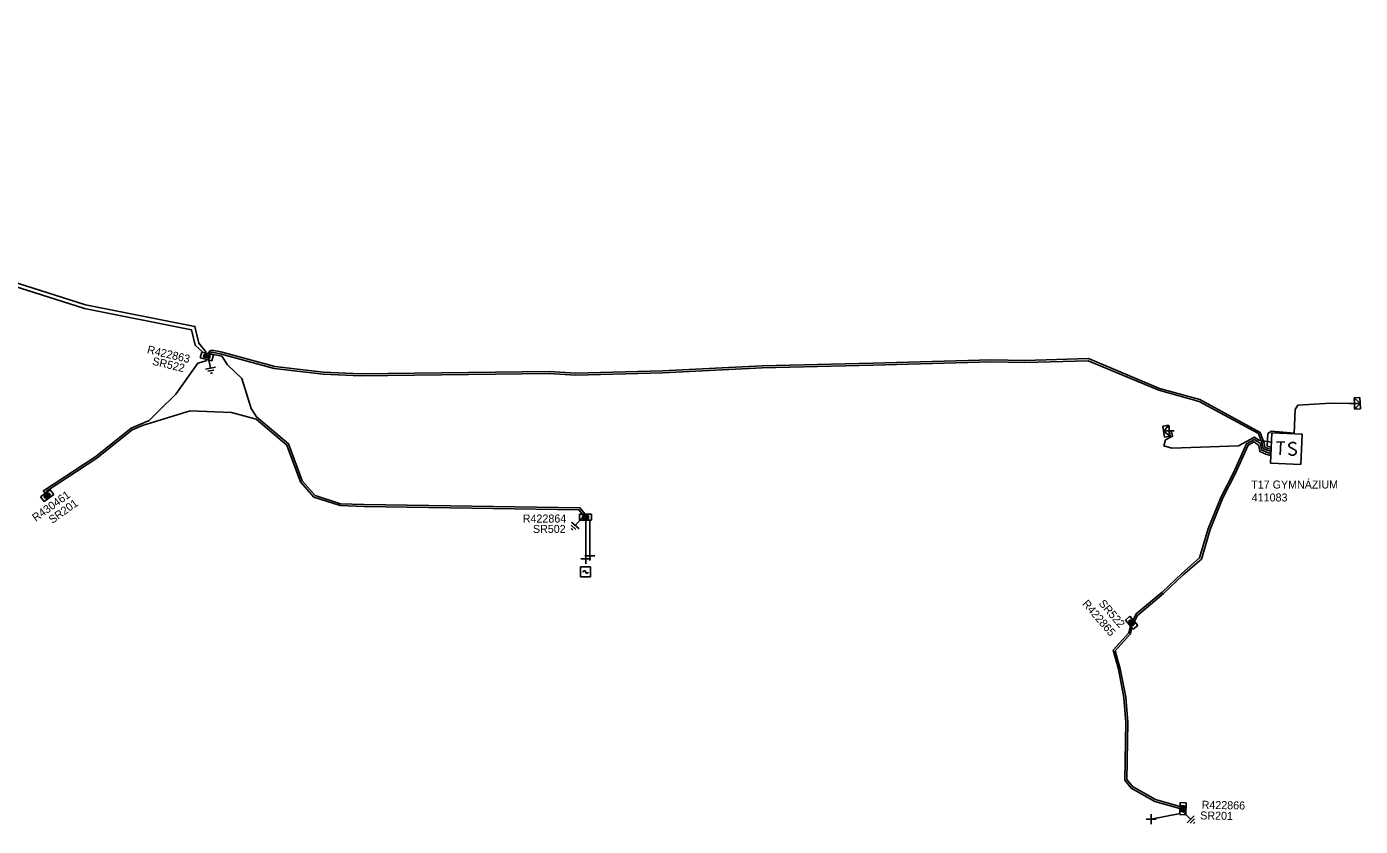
# Model space of a CAD drawing. Extents: x -540466 to -537383, y -1184038 to -1179972.
# Drawn here: x -537561.4 to -537394.7, y -1180860.1 to -1180760.2 of the extents above; entities that cross this region are included whole.
import ezdxf

# ---------------------------------------------------------------- set-up
doc = ezdxf.new("R2010")
doc.units = 0
for name, color, linetype in [('Vrstva 1', 7, 'Continuous'), ('Vrstva 14', 7, 'Continuous'), ('Vrstva 15', 7, 'Continuous'), ('Vrstva 25', 7, 'Continuous'), ('Vrstva 26', 7, 'Continuous'), ('Vrstva 27', 7, 'Continuous'), ('Vrstva 28', 7, 'Continuous'), ('Vrstva 29', 7, 'Continuous'), ('Vrstva 30', 7, 'Continuous'), ('Vrstva 31', 7, 'Continuous'), ('Vrstva 34', 7, 'Continuous'), ('Vrstva 5', 7, 'Continuous'), ('Vrstva 52', 7, 'Continuous'), ('Vrstva 59', 7, 'Continuous'), ('Vrstva 6', 7, 'Continuous'), ('Vrstva 8', 7, 'Continuous'), ('Vrstva 9', 7, 'Continuous')]:
    doc.layers.add(name, color=color, linetype=linetype)

# ---------------------------------------------------------------- blocks, each defined once
blk = doc.blocks.new('NN800')
at = {"layer": 'Vrstva 1'}
for points in [[(-0.44, 0.44), (0.44, -0.44)], [(-0.44, -0.44), (0.44, 0.44)]]:
    blk.add_lwpolyline(points, dxfattribs=at)
blk = doc.blocks.new('NN620')
at = {"layer": 'Vrstva 8'}
for points in [[(0.75, 0), (-0.75, 0)], [(-0.75, 0), (-0.75, -0.75)], [(0.75, -0.75), (0.75, 0)], [(-0.75, -0.75), (0.75, -0.75)], [(0.37, -0.18), (-0.38, -0.18)], [(-0.38, -0.18), (-0.38, -0.56)], [(-0.38, -0.56), (0.37, -0.56)], [(0.32, -0.23), (-0.33, -0.23)], [(-0.33, -0.23), (-0.33, -0.51)], [(-0.33, -0.51), (0.32, -0.51)], [(0.27, -0.27), (-0.28, -0.27)], [(-0.28, -0.27), (-0.28, -0.46)], [(-0.28, -0.46), (0.27, -0.46)], [(0.23, -0.32), (-0.23, -0.32)], [(-0.23, -0.32), (-0.23, -0.42)], [(-0.23, -0.42), (0.23, -0.42)], [(-0.19, -0.37), (0.19, -0.37)], [(0.23, -0.42), (0.23, -0.32)], [(0.27, -0.46), (0.27, -0.27)], [(0.32, -0.51), (0.32, -0.23)], [(0.37, -0.56), (0.37, -0.18)]]:
    blk.add_lwpolyline(points, dxfattribs=at)
blk = doc.blocks.new('NN630')
at = {"layer": 'Vrstva 9'}
for points in [[(0, -0.7), (-0.7, 0)], [(-0.7, -0.7), (-0.7, 0), (0.7, 0), (0.7, -0.7)], [(-0.7, -0.7), (0.7, -0.7)], [(0, -0.7), (0.7, 0)]]:
    blk.add_lwpolyline(points, dxfattribs=at)
blk = doc.blocks.new('NN810')
at = {"layer": 'Vrstva 14'}
for points in [[(0, -0.64), (0, -1.89)], [(0.63, -1.89), (-0.62, -1.89)], [(0.39, -2.2), (-0.4, -2.2)], [(0, -2.52), (-0.12, -2.52)], [(0.14, -2.52), (0, -2.52)]]:
    blk.add_lwpolyline(points, dxfattribs=at)
blk = doc.blocks.new('NN740')
at = {"layer": 'Vrstva 1'}
for points in [[(0.62, 0.62), (-0.63, 0.62)], [(-0.63, 0.62), (-0.63, -0.63)], [(0, 0), (0, 0.01), (0, 0.03), (-0.01, 0.05), (-0.01, 0.06), (-0.02, 0.08), (-0.03, 0.09), (-0.04, 0.1), (-0.05, 0.11), (-0.06, 0.12), (-0.08, 0.13), (-0.09, 0.14), (-0.11, 0.14), (-0.12, 0.15), (-0.14, 0.15), (-0.15, 0.15), (-0.17, 0.15), (-0.18, 0.15), (-0.2, 0.15), (-0.21, 0.14), (-0.23, 0.13), (-0.24, 0.12), (-0.26, 0.11), (-0.27, 0.1), (-0.28, 0.09), (-0.29, 0.08), (-0.29, 0.06), (-0.3, 0.05), (-0.3, 0.03), (-0.31, 0.02), (-0.31, 0), (-0.31, 0)], [(0.62, -0.63), (0.62, 0.62)], [(-0.63, -0.63), (0.62, -0.63)], [(0, 0), (0, -0.02), (0, -0.03), (0.01, -0.05), (0.01, -0.06), (0.02, -0.08), (0.03, -0.09), (0.04, -0.1), (0.05, -0.11), (0.06, -0.12), (0.07, -0.13), (0.09, -0.14), (0.1, -0.15), (0.12, -0.15), (0.13, -0.15), (0.15, -0.15), (0.16, -0.15), (0.18, -0.15), (0.19, -0.15), (0.21, -0.14), (0.22, -0.14), (0.24, -0.13), (0.25, -0.12), (0.26, -0.11), (0.27, -0.09), (0.28, -0.08), (0.29, -0.07), (0.29, -0.05), (0.3, -0.04), (0.3, -0.02), (0.3, -0.01), (0.3, -0.01)]]:
    blk.add_lwpolyline(points, dxfattribs=at)
blk = doc.blocks.new('NN640')
at = {"layer": 'Vrstva 6'}
for points in [[(-1.89, 1.89), (1.89, 1.89)], [(-1.89, -1.89), (-1.89, 1.89)], [(1.89, 1.89), (1.89, -1.89)], [(-1.26, 0.79), (-0.22, 0.79)], [(-0.73, 0.79), (-0.73, -0.79)], [(1.2, 0.66), (0.94, 0.79), (0.66, 0.79), (0.41, 0.66), (0.28, 0.47), (0.28, 0.41), (0.41, 0.22), (1.13, -0.16), (1.26, -0.32), (1.26, -0.47), (1.13, -0.66), (0.91, -0.79), (0.63, -0.79), (0.5, -0.73), (0.28, -0.6)], [(1.89, -1.89), (-1.89, -1.89)]]:
    blk.add_lwpolyline(points, dxfattribs=at)

msp = doc.modelspace()

# ---------------------------------------------------------------- linework, layer by layer
at = {"layer": 'Vrstva 5'}
for points in [[(-537539.27, -1180800.97), (-537540.33, -1180800.01), (-537540.77, -1180798.09), (-537554.14, -1180795.43), (-537572.94, -1180789.46), (-537579.99, -1180786.34), (-537583.4, -1180794.6), (-537583.56, -1180794.69), (-537583.6, -1180794.52), (-537580.17, -1180786.23), (-537584.61, -1180784.3), (-537592.51, -1180779.99), (-537605.42, -1180772.39), (-537614.61, -1180766.01), (-537620.35, -1180761.52), (-537621.15, -1180761.13), (-537621.78, -1180760.86), (-537622.41, -1180760.33)], [(-537539, -1180801.01), (-537538.98, -1180800.82), (-537539.87, -1180799.75), (-537540.35, -1180797.67), (-537554.02, -1180794.95), (-537572.76, -1180789), (-537584.39, -1180783.86), (-537592.27, -1180779.55), (-537605.16, -1180771.97), (-537614.31, -1180765.61), (-537620.03, -1180761.14), (-537621, -1180760.93), (-537621.67, -1180760.69), (-537622.25, -1180760.23)], [(-537538.74, -1180801.06), (-537538.46, -1180800.72), (-537538.21, -1180800.61), (-537537.13, -1180800.82), (-537530.39, -1180802.67), (-537524.33, -1180803.38), (-537519.64, -1180803.57), (-537496.09, -1180803.31), (-537492.78, -1180803.49), (-537481.94, -1180803.2), (-537469.47, -1180802.6), (-537455.67, -1180802.25), (-537440.83, -1180801.84), (-537436.67, -1180801.93), (-537428.72, -1180801.69), (-537419.84, -1180805.4), (-537414.79, -1180806.81), (-537407.24, -1180810.9), (-537406.74, -1180812.23), (-537406.65, -1180812.75), (-537406.29, -1180812.9), (-537405.94, -1180812.99)], [(-537538.48, -1180801.12), (-537538.32, -1180800.94), (-537538.18, -1180800.88), (-537537.19, -1180801.07), (-537530.44, -1180802.91), (-537524.35, -1180803.62), (-537519.64, -1180803.82), (-537496.09, -1180803.56), (-537492.78, -1180803.74), (-537481.93, -1180803.45), (-537469.47, -1180802.85), (-537455.67, -1180802.5), (-537440.83, -1180802.09), (-537436.67, -1180802.18), (-537428.76, -1180801.95), (-537419.92, -1180805.64), (-537414.89, -1180807.05), (-537407.46, -1180811.06), (-537406.99, -1180812.28), (-537406.87, -1180812.92), (-537406.37, -1180813.14), (-537405.95, -1180813.25)], [(-537491.58, -1180821.1), (-537492.25, -1180820.32), (-537519.19, -1180819.92), (-537522.15, -1180819.81), (-537525.35, -1180818.77), (-537526.94, -1180816.95), (-537528.66, -1180812.33), (-537532.65, -1180808.97), (-537533.31, -1180807.91), (-537534.5, -1180804.16), (-537536.29, -1180802.47), (-537537, -1180801.36), (-537538.23, -1180801.12), (-537538.29, -1180801.16)], [(-537538.91, -1180801.8), (-537538.94, -1180801.96), (-537540, -1180802.24), (-537542.72, -1180806.12), (-537544.8, -1180808.13), (-537546.07, -1180809.4), (-537548.33, -1180810.36), (-537552.75, -1180813.91), (-537559.28, -1180818.2), (-537559.06, -1180818.48)], [(-537558.86, -1180818.34), (-537558.92, -1180818.26), (-537552.61, -1180814.11), (-537548.19, -1180810.58), (-537546.91, -1180810.05), (-537540.94, -1180808.21), (-537535.77, -1180808.4), (-537532.72, -1180809.25), (-537528.88, -1180812.49), (-537527.16, -1180817.07), (-537525.49, -1180818.99), (-537522.19, -1180820.05), (-537519.19, -1180820.17), (-537492.37, -1180820.56), (-537491.91, -1180821.1)], [(-537423.1, -1180834.34), (-537422.74, -1180833.56), (-537419.49, -1180830.86), (-537417.03, -1180828.53), (-537414.82, -1180826.59), (-537413.73, -1180822.93), (-537412.14, -1180818.96), (-537410.59, -1180815.97), (-537408.96, -1180812.31), (-537407.98, -1180811.79), (-537407.23, -1180812.3), (-537407.09, -1180813.1), (-537406.45, -1180813.38), (-537406.04, -1180813.49), (-537405.96, -1180813.49)], [(-537422.95, -1180834.52), (-537422.58, -1180833.76), (-537419.33, -1180831.04), (-537416.87, -1180828.71), (-537414.6, -1180826.73), (-537413.49, -1180823.01), (-537411.92, -1180819.06), (-537410.37, -1180816.07), (-537408.76, -1180812.49), (-537408.02, -1180812.1), (-537407.43, -1180812.52), (-537407.31, -1180813.27), (-537406.53, -1180813.62), (-537406.07, -1180813.73), (-537405.96, -1180813.74)], [(-537417.3, -1180857.88), (-537420.41, -1180856.99), (-537423.37, -1180855.35), (-537424.18, -1180854.33), (-537424.05, -1180847.15), (-537424.28, -1180844), (-537424.97, -1180840.48), (-537425.64, -1180838.12), (-537423.66, -1180835.95), (-537423.45, -1180835.16)], [(-537417.3, -1180857.62), (-537420.31, -1180856.75), (-537423.21, -1180855.15), (-537423.92, -1180854.25), (-537423.8, -1180847.15), (-537424.04, -1180843.96), (-537424.73, -1180840.42), (-537425.36, -1180838.18), (-537423.48, -1180836.11), (-537423.27, -1180835.37)]]:
    msp.add_lwpolyline(points, dxfattribs=at)
at = {"layer": 'Vrstva 52'}
for points in [[(-537405.94, -1180812.74), (-537406.37, -1180812.62), (-537406.28, -1180811.04), (-537405.82, -1180810.75), (-537403, -1180810.99), (-537402.87, -1180808.04), (-537402.53, -1180807.48), (-537398.45, -1180807.23), (-537395.46, -1180807.29)], [(-537405.87, -1180812.11), (-537407.42, -1180811.87), (-537407.97, -1180811.49), (-537409.95, -1180812.57), (-537418.31, -1180812.86), (-537419.28, -1180812.59), (-537419.07, -1180811.84), (-537418.19, -1180811.39), (-537418.39, -1180810.67), (-537418.61, -1180810.69)]]:
    msp.add_lwpolyline(points, dxfattribs=at)
at = {"layer": 'Vrstva 59'}
for points in [[(-537491.49, -1180821.85), (-537491.51, -1180826.7)], [(-537491.02, -1180821.86), (-537491.02, -1180826.3)], [(-537417.25, -1180858.51), (-537420.86, -1180859.23)]]:
    msp.add_lwpolyline(points, dxfattribs=at)

# ---------------------------------------------------------------- block references
at = {"layer": 'Vrstva 15'}
for p, rotation in [((-537538.78, -1180801.03), 11.175980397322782), ((-537491.56, -1180821.13), -42.231711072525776), ((-537417.28, -1180857.89), 44.99999995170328)]:
    msp.add_blockref('NN810', p, dxfattribs=dict(at, rotation=rotation))
at = {"layer": 'Vrstva 25', "rotation": -2.259422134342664}
msp.add_blockref('NN640', (-537403.98, -1180812.93), dxfattribs=at)
at = {"layer": 'Vrstva 28'}
for p, rotation in [((-537538.78, -1180801.04), -13.436633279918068), ((-537559.04, -1180818.5), 35.721227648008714), ((-537423.04, -1180834.44), -49.09191936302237), ((-537417.28, -1180857.89), 88.96100838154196)]:
    msp.add_blockref('NN620', p, dxfattribs=dict(at, rotation=rotation))
msp.add_blockref('NN620', (-537491.56, -1180821.13), dxfattribs=at)
at = {"layer": 'Vrstva 31'}
for p, rotation in [((-537395.46, -1180807.29), 92.26042230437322), ((-537418.61, -1180810.69), -80.60970000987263)]:
    msp.add_blockref('NN630', p, dxfattribs=dict(at, rotation=rotation))
at = {"layer": 'Vrstva 34', "rotation": 45}
for p in [(-537395.46, -1180807.29), (-537418.61, -1180810.69), (-537491.51, -1180826.7), (-537491.02, -1180826.3), (-537420.86, -1180859.23)]:
    msp.add_blockref('NN800', p, dxfattribs=at)
at = {"layer": 'Vrstva 34'}
msp.add_blockref('NN740', (-537491.54, -1180828.33), dxfattribs=at)

# ---------------------------------------------------------------- texts
at = {"layer": 'Vrstva 26'}
msp.add_text('411083', height=1, dxfattribs=at).set_placement((-537408.3, -1180819.53))
at = {"layer": 'Vrstva 27'}
msp.add_text('T17 GYMNÁZIUM', height=1, rotation=0.066, dxfattribs=at).set_placement((-537408.37, -1180817.92))
at = {"layer": 'Vrstva 29'}
for s, rotation, p in [('R422863', 346.563, (-537546.39, -1180800.99)), ('R430461', 35.721, (-537560.24, -1180822.09)), ('R422865', 310.908, (-537429.54, -1180832.36)), ('R422866', 358.961, (-537414.57, -1180857.91))]:
    msp.add_text(s, height=1, rotation=rotation, dxfattribs=at).set_placement(p)
msp.add_text('R422864', height=1, dxfattribs=at).set_placement((-537499.39, -1180822.16))
at = {"layer": 'Vrstva 30'}
for s, rotation, p in [('SR522', 346.563, (-537545.75, -1180802.44)), ('SR201', 35.721, (-537558.17, -1180822.35)), ('SR522', 310.908, (-537427.49, -1180832.31)), ('SR201', 358.961, (-537414.75, -1180859.24))]:
    msp.add_text(s, height=1, rotation=rotation, dxfattribs=at).set_placement(p)
msp.add_text('SR502', height=1, dxfattribs=at).set_placement((-537498.12, -1180823.46))

doc.saveas('drawing.dxf')
